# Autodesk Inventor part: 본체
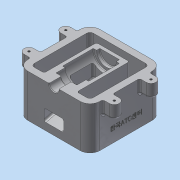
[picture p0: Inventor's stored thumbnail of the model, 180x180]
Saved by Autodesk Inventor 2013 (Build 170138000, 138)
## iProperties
Created: 2018-01
Part Number: 본체
Material: 알루미늄 6061
Document SubType Name: Modeling
Designer: dgall
Density: 2.71 g/cm^3
Mass: 998.262 g
Surface Area: 836.256 cm^2
Volume: 368.362 cm^3
Author: dgall
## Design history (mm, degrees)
sketch "스케치1"
  geometry: L1 (-55, 55)-(55, 55); L2 (55, 55)-(55, -55); L3 (55, -55)-(-55, -55); L4 (-55, -55)-(-55, 55); L5 (45, 45)-(-45, 45); L6 (-45, 45)-(-45, -45); L7 (-45, -45)-(45, -45); L8 (45, -45)-(45, 45); 3 further points
  constraints: 16 end point, 2 midpoint, 2 parallel, 1 horizontal, 1 horizontal alignment, 1 perpendicular, 1 vertical alignment
  dimensions: "d0" = 110 distance of L1.start L1.end; "d2" = 110 distance of L1.end L2.end; "d3" = 10 distance between parallel lines of L1 L5; "d4" = 10 distance between parallel lines of L4 L6; "d5" = 10 distance between parallel lines of L2 L8; "d6" = 10 distance between parallel lines of L3 L7
extrude "돌출1" new body sketch "스케치1" stored distance "d7" = 65; taper "d8" = 0 deg
sketch "스케치3"
  geometry: L1 (-45, -32.5)-(-45, 32.5) reference; L2 (45, -32.5)-(-45, -32.5) reference; L3 (45, -32.5)-(45, 32.5) reference; L4 (-45, 32.5)-(45, 32.5) reference; L5 (35, 32.5)-(35, -2.5); L6 (35, -2.5)-(-45, -23.936); L7 (55, -32.5)-(55, 32.5) reference; 1 further point
  constraints: 4 end point, 2 point on line, 1 perpendicular
  dimensions: "d9" = 20 distance between parallel lines of L7 L5; "d10" = 30 distance from line of L2 L5.end; "d11" = 105 deg angle of L6 L1
extrude "돌출2" join sketch "스케치3" stored distance "d12" = 50; taper "d13" = 0 deg
sketch "스케치4"
  geometry: L1 (-55, 55)-(-55, -55) reference; L2 (-55, -55)-(55, -55) reference; L3 (55, -55)-(55, 55) reference; L4 (-55, -35.5)-(-65, -35.5); L5 (-65, -20.5)-(-55, -20.5); L6 (-55, 20.5)-(-65, 20.5); L7 (-65, 35.5)-(-55, 35.5); A1 r 7.5 centre (-65, -28) between (-65, -20.5) and (-65, -35.5); A2 r 7.5 centre (-65, 28) between (-65, 35.5) and (-65, 20.5); 1 further point
  constraints: 8 end point, 4 perpendicular, 4 point on circle, 4 point on line, 4 tangent, 2 centre point, 2 vertical alignment, 1 equal radius, 1 parallel
  dimensions: "d14" = 7.5 radius of A1; "d16" = 27 distance from line of L2 A1.centre; "d17" = 56 distance of A2.centre A1.centre; "d18" = 10 distance of L5.start L5.end
extrude "돌출3" join sketch "스케치4" distance "d19" = 20; taper "d20" = 0 deg
sketch "스케치6"
  geometry: L1 (-45, 32.5)-(-45, -23.936) reference; L2 (-45, 32.5)-(35, 32.5) reference; L3 (35, 32.5)-(35, -2.5) reference; L4 (35, -2.5)-(-45, -23.936) reference; L5 (-20.5, 12.5)-(-20.5, 32.5) reference; L6 (20.5, 32.5)-(-20.5, 32.5) reference; L7 (20.5, 32.5)-(20.5, 12.5) reference; L8 (20.5, 12.5)-(35.5, 12.5) reference; L9 (35.5, 12.5)-(35.5, 32.5) reference; L10 (55, 32.5)-(35.5, 32.5) reference; L11 (55, -32.5)-(55, 32.5) reference; L12 (-55, -32.5)-(55, -32.5) reference; L13 (-55, 32.5)-(-55, -32.5) reference; L14 (-35.5, 32.5)-(-55, 32.5) reference; L15 (-35.5, 32.5)-(-35.5, 12.5) reference; L16 (-35.5, 12.5)-(-20.5, 12.5) reference; L17 (-55, 32.5)-(35.5, 32.5); L18 (-55, 32.5)-(-55, 25); L19 (-55, 25)-(-36, 25); L20 (-36, 25)-(-36, 16.5); L21 (-36, 16.5)-(-22, 16.5); L22 (-22, 16.5)-(-22, 12.5); L23 (-22, 12.5)-(25, 12.5); L24 (25, 12.5)-(25, 17.5); L25 (25, 17.5)-(30, 17.5); L26 (30, 17.5)-(30, 32.5); 1 further point
  constraints: 20 end point, 5 perpendicular, 4 parallel, 2 point on line
  dimensions: "d21" = 7.5 distance between parallel lines of L14 L19; "d22" = 16 distance between parallel lines of L2 L21; "d23" = 20 distance between parallel lines of L2 L23; "d24" = 15 distance between parallel lines of L6 L25; "d25" = 19 distance of L18.end L19.end; "d26" = 14 distance of L20.end L21.end; "d27" = 47 distance of L22.end L23.end; "d28" = 5 distance of L24.end L25.end
revolve "회전1" sketch "스케치6" stored, may be unused: angle "d29" = 90 deg
sketch "스케치7"
  geometry: L1 (35, -2.5)-(-45, -23.936) reference; L2 (20, -1.343)-(-55, -21.439); L3 (-20.5, 12.5)-(-20.5, 32.5) reference; L4 (20.5, 32.5)-(-20.5, 32.5) reference; L5 (20.5, 32.5)-(20.5, 12.5) reference; L6 (20.5, 12.5)-(35.5, 12.5) reference; L7 (35.5, 12.5)-(35.5, 32.5) reference; L8 (55, 32.5)-(35.5, 32.5) reference; L9 (55, -32.5)-(55, 32.5) reference; L10 (-55, -32.5)-(55, -32.5) reference; L11 (-55, 32.5)-(-55, -32.5) reference; L12 (-35.5, 32.5)-(-55, 32.5) reference; L13 (-35.5, 32.5)-(-35.5, 12.5) reference; L14 (-35.5, 12.5)-(-20.5, 12.5) reference; L15 (-17, 6.743)-(-55, -3.439); L16 (20, -1.343)-(20, 20.901); L17 (-22, 12.5)-(-22, 32.5) reference; L18 (-55, -3.439)-(-55, -21.439); L19 (-17, 6.743)-(-17, 20.901); L20 (-17, 20.901)-(20, 20.901); 1 further point
  constraints: 12 end point, 2 parallel, 2 perpendicular, 2 point on line
  dimensions: "d30" = 5 distance between parallel lines of L1 L2; "d32" = 18 distance of L2.end L15.end; "d33" = 75 deg angle of L11 L15; "d36" = 37 distance of L19.end L16.end; "d37" = 5 distance between parallel lines of L19 L17; "d38" = 22.24378 distance from line of L2.start L20
extrude "돌출4" cut sketch "스케치7" stored distance "d39" = 30; taper "d40" = 0 deg
fillet "모깎기1" dims "d41" = 1
chamfer "모따기1" distance "d42" = 1; stored, may be unused: second distance "d43" = 2, angle "d44" = 45 deg
fillet "모깎기3" dims "d46" = 3
fillet "모깎기4" dims "d47" = 3
fillet "모깎기5" dims "d48" = 3
fillet "모깎기6" dims "d49" = 15
fillet "모깎기7" dims "d50" = 5
sketch "스케치9" dims "d0" = 110, "d2" = 110, "d3" = 10, "d4" = 10, "d5" = 10, "d6" = 10
  geometry: L1 (0, 80)-(0, 0) reference; L2 (-65, -15)-(0, -15) reference; 2 further points
  constraints: 1 other
  dimensions: "d53" = 55 distance from line of point (-20, 40) L2; "d54" = 20 distance from line of L1 point (-20, 40)
feature "엠보싱1" sketch "스케치9" dims "d0" = 110, "d2" = 110, "d3" = 10, "d4" = 10, "d5" = 10, "d6" = 10, "d55" = 0.5, "d56" = 0
sketch "스케치10"
  geometry: A1 r 7.5 centre (65, -28) between (65, -35.5) and (65, -20.5) reference; A2 r 7.5 centre (65, 28) between (65, 20.5) and (65, 35.5) reference; A3 r 7.5 centre (-65, 28) between (-65, 35.5) and (-65, 20.5) reference; A4 r 7.5 centre (-65, -28) between (-65, -20.5) and (-65, -35.5) reference; 5 further points
  constraints: 4 coincident
hole "구멍1" sketch "스케치10" at (-65, -28), (-65, 28), (65, 28), (65, -28) diameter "d57" = 3.242; stored, may be unused: countersink angle "d61" = 90 deg, drill point angle "d63" = 118 deg; dims "d58" = 9, "d59" = 4, "d60" = 2, "d62" = 11
fillet "모깎기10" dims "d64" = 3
fillet "모깎기11" dims "d65" = 3
fillet "모깎기12" dims "d66" = 3
fillet "모깎기13" dims "d67" = 3
fillet "모깎기14" dims "d68" = 3
fillet "모깎기15" dims "d69" = 3
fillet "모깎기17" dims "d71" = 3
fillet "모깎기18" dims "d72" = 3
fillet "모깎기19" dims "d73" = 3
fillet "모깎기20" dims "d74" = 3
node "솔리드1"
mirror "대칭1"
node "투영된 루프1"
node "투영된 루프2"
node "투영된 루프3"
node "투영된 루프4"
